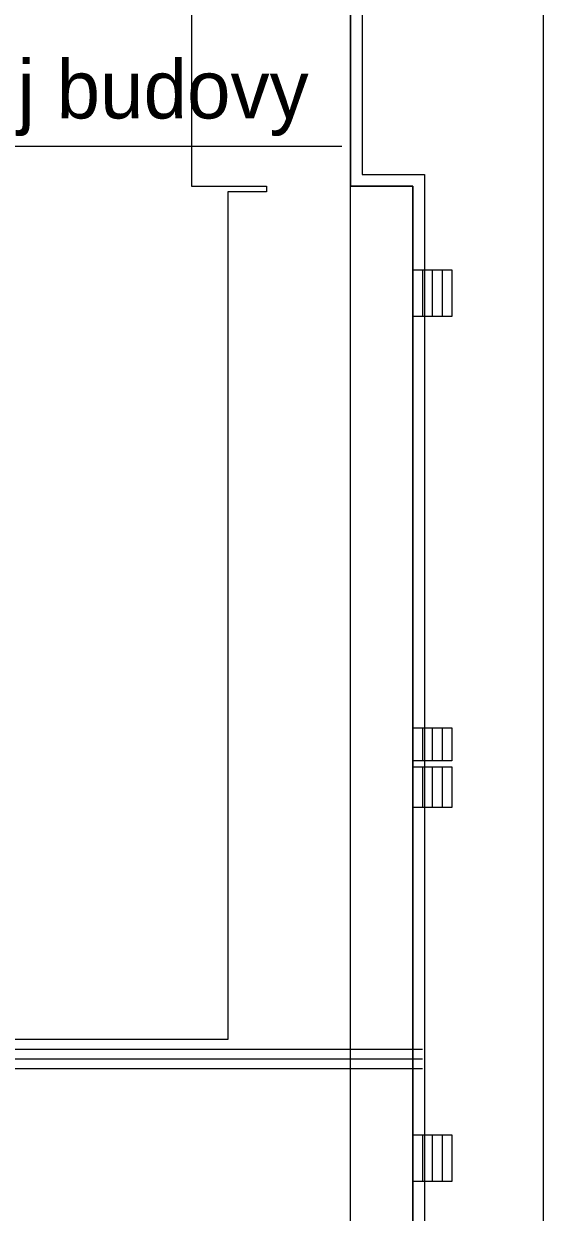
# Model space of a CAD drawing. Extents: x -263993 to -263783, y -1242294 to -1242146.
# Drawn here: x -263902 to -263888.67, y -1242207.77 to -1242177.26 of the extents above; entities that cross this region are included whole.
import ezdxf

# ---------------------------------------------------------------- set-up
doc = ezdxf.new("R2010")
doc.units = 0
doc.layers.add('KFA_2D_SITUACIA_DSP', color=7, linetype='Continuous')
doc.layers.add('POPIS', color=7, linetype='Continuous')

msp = doc.modelspace()

# ---------------------------------------------------------------- linework, layer by layer
at = {"layer": 'KFA_2D_SITUACIA_DSP'}
for p, q in [((-263893.618, -1242181.432), (-263893.618, -1242147.332)), ((-263888.673, -1242164.687), (-263888.673, -1242220.396)), ((-263893.318, -1242166.082), (-263893.318, -1242181.132)), ((-263893.618, -1242210.482), (-263893.618, -1242166.382)), ((-263893.618, -1242166.382), (-263893.618, -1242181.432)), ((-263897.693, -1242168.582), (-263897.693, -1242181.432)), ((-263893.318, -1242181.132), (-263891.718, -1242181.132)), ((-263891.718, -1242181.132), (-263891.718, -1242220.206)), ((-263897.693, -1242181.432), (-263895.768, -1242181.432)), ((-263895.768, -1242181.432), (-263895.768, -1242181.582)), ((-263892.018, -1242181.432), (-263893.618, -1242181.432)), ((-263893.618, -1242181.432), (-263892.018, -1242181.432)), ((-263892.018, -1242220.33), (-263892.018, -1242181.432)), ((-263892.018, -1242181.432), (-263892.018, -1242220.33)), ((-263895.768, -1242181.582), (-263896.768, -1242181.582)), ((-263896.768, -1242181.582), (-263896.768, -1242203.332)), ((-263892.018, -1242183.583), (-263891.018, -1242183.583)), ((-263891.768, -1242183.583), (-263891.768, -1242184.781)), ((-263891.518, -1242183.583), (-263891.518, -1242184.781)), ((-263891.268, -1242183.583), (-263891.268, -1242184.781)), ((-263891.018, -1242183.583), (-263891.018, -1242184.781)), ((-263891.018, -1242184.781), (-263892.018, -1242184.781)), ((-263892.018, -1242195.333), (-263891.018, -1242195.333)), ((-263891.768, -1242195.333), (-263891.768, -1242196.181)), ((-263891.518, -1242195.333), (-263891.518, -1242196.181)), ((-263891.268, -1242195.333), (-263891.268, -1242196.181)), ((-263891.018, -1242195.333), (-263891.018, -1242196.181)), ((-263891.018, -1242196.181), (-263892.018, -1242196.181)), ((-263892.018, -1242196.333), (-263891.018, -1242196.333)), ((-263891.768, -1242196.333), (-263891.768, -1242197.381)), ((-263891.518, -1242196.333), (-263891.518, -1242197.381)), ((-263891.268, -1242196.333), (-263891.268, -1242197.381)), ((-263891.018, -1242196.333), (-263891.018, -1242197.381)), ((-263891.018, -1242197.381), (-263892.018, -1242197.381)), ((-263896.768, -1242203.332), (-263909.118, -1242203.332)), ((-263910.004, -1242203.582), (-263891.768, -1242203.582)), ((-263910.211, -1242204.082), (-263891.768, -1242204.082)), ((-263910.108, -1242203.832), (-263891.768, -1242203.832)), ((-263892.018, -1242205.783), (-263891.018, -1242205.783)), ((-263891.768, -1242205.783), (-263891.768, -1242206.981)), ((-263891.518, -1242205.783), (-263891.518, -1242206.981)), ((-263891.268, -1242205.783), (-263891.268, -1242206.981)), ((-263891.018, -1242205.783), (-263891.018, -1242206.981)), ((-263891.018, -1242206.981), (-263892.018, -1242206.981))]:
    msp.add_line(p, q, dxfattribs=at)
at = {"layer": 'POPIS'}
msp.add_line((-263908.376, -1242180.404), (-263893.837, -1242180.404), dxfattribs=at)

# ---------------------------------------------------------------- texts
msp.add_text('hlavnej budovy', height=1.5, dxfattribs=at).set_placement((-263908.071, -1242179.695))

doc.saveas('drawing.dxf')
